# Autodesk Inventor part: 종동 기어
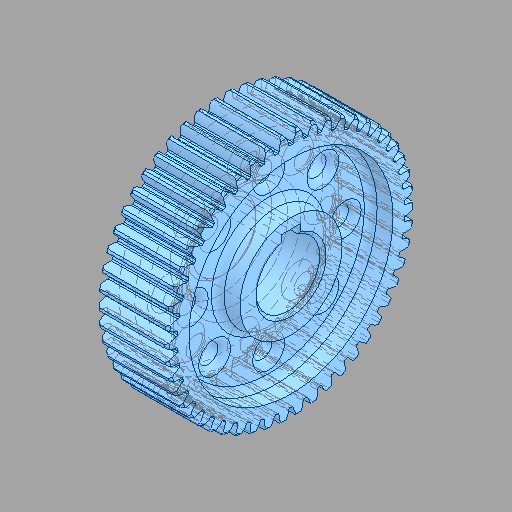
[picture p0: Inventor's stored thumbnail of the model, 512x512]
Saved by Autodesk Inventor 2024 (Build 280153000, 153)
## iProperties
Created: 2025-11
Part Number: 종동 기어
Material: 강철, 탄소
Document SubType Name: Modeling
Designer: Edu09
Density: 7.85 g/cm^3
Appearance: 기본값
Author: jhkim
Sending System: Autodesk Inventor 2026
Preprocessor: ST-DEVELOPER v20.1
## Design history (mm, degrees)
feature "솔리드1"
node "솔리드2"
